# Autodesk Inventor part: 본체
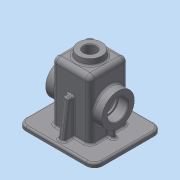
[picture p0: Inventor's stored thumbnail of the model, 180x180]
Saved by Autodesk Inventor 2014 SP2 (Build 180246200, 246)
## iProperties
Created: 2016-08
Part Number: 본체
Material: 일반
Document SubType Name: Modeling
Designer: user
Density: 1 g/cm^3
Appearance: 기본값
Author: user
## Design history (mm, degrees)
sketch "스케치1"
  geometry: L1 (-32.5, 32.5)-(32.5, 32.5); L2 (32.5, 32.5)-(32.5, -32.5); L3 (32.5, -32.5)-(-32.5, -32.5); L4 (-32.5, -32.5)-(-32.5, 32.5); L5 (-32.5, 32.5)-(32.5, -32.5); L6 (32.5, 32.5)-(-32.5, -32.5); 1 further point
  constraints: 12 end point, 2 midpoint, 2 parallel, 1 horizontal, 1 perpendicular
  dimensions: "d0" = 65 distance of L2.end L3.end; "d1" = 65 distance of L1.end L2.end
extrude "돌출1" new body sketch "스케치1" distance "d2" = 100; taper "d3" = 0 deg
sketch "스케치2"
  geometry: L1 (-65, 57.5)-(65, 57.5); L2 (65, 57.5)-(65, -57.5); L3 (65, -57.5)-(-65, -57.5); L4 (-65, -57.5)-(-65, 57.5); L5 (-65, 57.5)-(65, -57.5); L6 (65, 57.5)-(-65, -57.5); 1 further point
  constraints: 12 end point, 2 midpoint, 2 parallel, 1 horizontal, 1 perpendicular
  dimensions: "d4" = 130 distance of L2.end L3.end; "d5" = 115 distance of L1.end L2.end
extrude "돌출2" join sketch "스케치2" distance "d6" = 10; taper "d7" = 0 deg
fillet "모깎기1" dims "d8" = 8
fillet "모깎기2" dims "d9" = 8
feature "쉘1" dims "d10" = 5
sketch "스케치3"
  geometry: L1 (35.5, -80)-(84.5, -80) reference; L2 (87.5, -77)-(87.5, -28) reference; L3 (84.5, -25)-(35.5, -25) reference; L4 (32.5, -28)-(32.5, -77) reference; L5 (120, -105)-(0, -105) reference; L6 (0, -105)-(0, 0) reference; L7 (0, 0)-(120, 0) reference; L8 (120, 0)-(120, -105) reference; A1 r 3 centre (84.5, -77) between (84.5, -80) and (87.5, -77) reference; A2 r 3 centre (84.5, -28) between (87.5, -28) and (84.5, -25) reference; A3 r 3 centre (35.5, -28) between (35.5, -25) and (32.5, -28) reference; A4 r 3 centre (35.5, -77) between (32.5, -77) and (35.5, -80) reference; 1 further point
extrude "돌출3" join sketch "스케치3" stored distance "d11" = 10; taper "d12" = 0 deg
fillet "모깎기3" dims "d13" = 14
sketch "스케치4"
  geometry: L1 (-51, -57.5)-(51, -57.5) reference; L2 (65, -43.5)-(65, 43.5) reference; L3 (51, 57.5)-(-51, 57.5) reference; L4 (-65, 43.5)-(-65, -43.5) reference; L5 (-51, -52.5)-(51, -52.5); L6 (60, -43.5)-(60, 43.5); L7 (51, 52.5)-(-51, 52.5); L8 (-60, 43.5)-(-60, -43.5); A1 r 14 centre (51, -43.5) between (51, -57.5) and (65, -43.5) reference; A2 r 14 centre (51, 43.5) between (65, 43.5) and (51, 57.5) reference; A3 r 14 centre (-51, 43.5) between (-51, 57.5) and (-65, 43.5) reference; A4 r 14 centre (-51, -43.5) between (-65, -43.5) and (-51, -57.5) reference; A5 r 9 centre (51, -43.5) between (51, -52.5) and (60, -43.5); A6 r 9 centre (51, 43.5) between (60, 43.5) and (51, 52.5); A7 r 9 centre (-51, 43.5) between (-51, 52.5) and (-60, 43.5); A8 r 9 centre (-51, -43.5) between (-60, -43.5) and (-51, -52.5); 1 further point
  constraints: 8 end point, 8 point on circle, 4 centre point, 7 other
  dimensions: "d14" = 5 distance between parallel lines of L4 L8
extrude "돌출4" cut sketch "스케치4" distance "d15" = 3; taper "d16" = 0 deg
fillet "모깎기4" dims "d17" = 3
node "작업 평면1"
sketch "스케치5"
  geometry: C1 r 20 at (0, 0); 1 further point
  constraints: 1 centre point, 1 coincident
  dimensions: "d19" = 40 diameter of C1
extrude "돌출5" join sketch "스케치5" stored distance "d20" = 3; taper "d21" = 7 deg
hole "구멍1" diameter "d24" = 21; stored, may be unused: countersink angle "d28" = 90 deg, drill point angle "d30" = 118 deg; dims "d22" = 10, "d23" = 10, "d25" = 6, "d26" = 4, "d27" = 2, "d29" = 8
fillet "모깎기5" dims "d31" = 3
chamfer "모따기1" distance "d32" = 1; stored, may be unused: second distance "d33" = 2, angle "d34" = 45 deg
node "작업 평면2"
sketch "스케치7"
  geometry: L1 (10, 49)-(10, 0) reference; C1 r 27.5 at (-45, 24.5); 1 further point
  constraints: 1 centre point, 1 horizontal alignment
  dimensions: "d38" = 55 diameter of C1; "d39" = 55 distance from line of L1 C1.centre
extrude "돌출6" join sketch "스케치7" stored distance "d40" = 3; taper "d41" = 0 deg
hole "구멍2" diameter "d45" = 30; stored, may be unused: countersink angle "d49" = 90 deg, drill point angle "d51" = 118 deg; dims "d43" = 10, "d44" = 10, "d46" = 6, "d47" = 4, "d48" = 2, "d50" = 8
hole "구멍3" diameter "d54" = 35; stored, may be unused: countersink angle "d58" = 90 deg, drill point angle "d60" = 0 deg; dims "d52" = 10, "d53" = 10, "d55" = 6, "d56" = 4, "d57" = 2, "d59" = 17
fillet "모깎기7" dims "d61" = 0.3
chamfer "모따기2" distance "d62" = 1; stored, may be unused: second distance "d63" = 2, angle "d64" = 45 deg
fillet "모깎기8" dims "d65" = 0.3
chamfer "모따기3" distance "d66" = 1; stored, may be unused: second distance "d67" = 2, angle "d68" = 45 deg
sketch "스케치8"
  geometry: L1 (-47.5, 17.5)-(-32.5, 17.5) reference; L2 (51, 0)-(-51, 0) reference; L3 (-42.5, 17.5)-(-42.5, 0); L4 (-27.5, 92)-(-27.5, -10) reference; 1 further point
  constraints: 2 end point, 2 point on line, 1 perpendicular
  dimensions: "d69" = 15 distance from line of L4 L3.end
feature "리브1" sketch "스케치8" dims "d70" = 1, "d71" = 6, "d72" = 0, "d73" = 0, "d74" = 1, "d75" = 1
fillet "모깎기9" dims "d76" = 3
fillet "모깎기10" dims "d77" = 3
sketch "스케치9"
  geometry: L1 (-32.5, 92)-(-32.5, 0) reference; L2 (-54.5, 0)-(-43.5, 0) reference; L3 (-32.5, 60)-(-41.068, 60); L4 (-41.068, 60)-(-49.5, 0); L5 (-57.5, -3)-(-57.5, -7) reference; L6 (-52.5, -10)-(-43.5, -10) reference; 1 further point
  constraints: 4 end point, 2 point on line, 1 parallel
  dimensions: "d78" = 8 deg angle of L5 L4; "d79" = 70 distance from line of L6 L3.end; "d80" = 8 horizontal distance of L5.end L4.end
feature "리브2" sketch "스케치9" dims "d81" = 1, "d82" = 10, "d83" = 0, "d84" = 0, "d85" = 1, "d86" = 1
fillet "모깎기11" dims "d87" = 3
fillet "모깎기12" dims "d88" = 3
node "솔리드1"
mirror "대칭1"
mirror "대칭2"
mirror "대칭3"
mirror "대칭4"
other parameters: "d37" = 15
